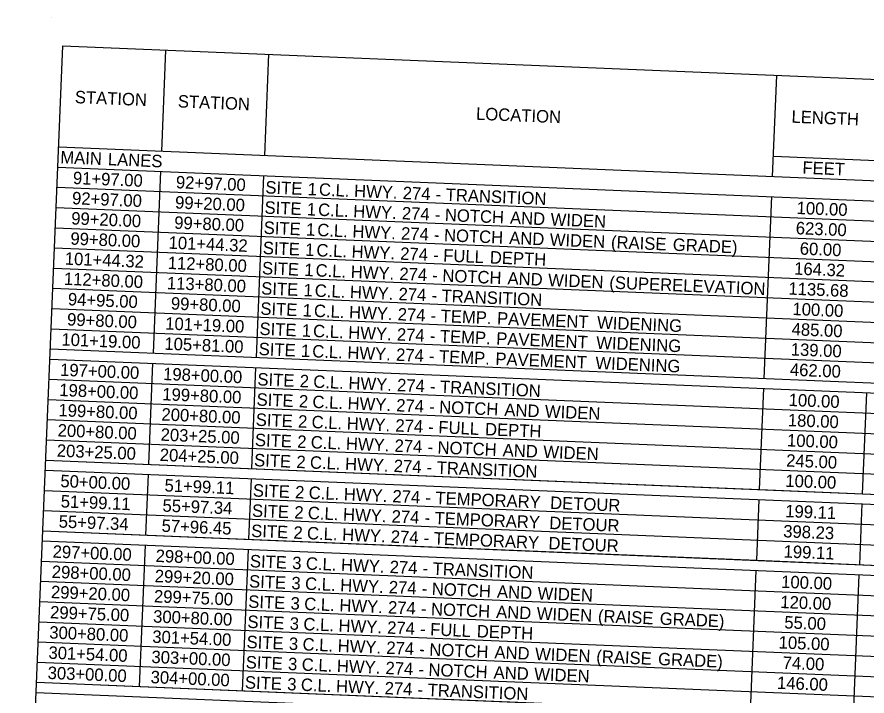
# Model space of a CAD drawing. Extents: x 1164179 to 1171425, y 1655958 to 1657208.
# Drawn here: x 1168004.2 to 1168414.3, y 1656519.5 to 1656846.8 of the extents above; entities that cross this region are included whole.
import ezdxf

# ---------------------------------------------------------------- set-up
doc = ezdxf.new("R2010")
doc.units = 0
doc.layers.add('Default', color=7, linetype='Continuous')

msp = doc.modelspace()

# ---------------------------------------------------------------- linework, layer by layer
at = {"layer": 'Default'}
for p, q in [((1168021.09, 1656846.81), (1168021.09, 1656846.81)), ((1168004.21, 1656297.14), (1168026.37, 1656832.93)), ((1168004.21, 1656297.14), (1168026.37, 1656832.93)), ((1168026.37, 1656832.93), (1169513.44, 1656771.41)), ((1168074.04, 1656782.16), (1168076.06, 1656830.87)), ((1168123.72, 1656780.11), (1168125.74, 1656828.82)), ((1168368.73, 1656769.97), (1168370.74, 1656818.68)), ((1168024.36, 1656784.22), (1169511.42, 1656722.7)), ((1168369.13, 1656779.72), (1168418.81, 1656777.66)), ((1168023.96, 1656774.48), (1169511.02, 1656712.96)), ((1168070.01, 1656684.75), (1168073.64, 1656772.42)), ((1168070.01, 1656684.75), (1168073.64, 1656772.42)), ((1168119.69, 1656682.69), (1168123.32, 1656770.37)), ((1168119.69, 1656682.69), (1168123.32, 1656770.37)), ((1168023.55, 1656764.74), (1169510.62, 1656703.22)), ((1168364.7, 1656672.56), (1168368.32, 1656760.23)), ((1168364.7, 1656672.56), (1168368.32, 1656760.23)), ((1168023.15, 1656754.99), (1169510.22, 1656693.48)), ((1168022.75, 1656745.25), (1169509.81, 1656683.74)), ((1168022.34, 1656735.51), (1169509.41, 1656673.99)), ((1168021.94, 1656725.77), (1169509.01, 1656664.25)), ((1168021.54, 1656716.03), (1169508.6, 1656654.51)), ((1168021.13, 1656706.29), (1169508.2, 1656644.77)), ((1168020.73, 1656696.54), (1169507.8, 1656635.03)), ((1168020.33, 1656686.8), (1169507.39, 1656625.29)), ((1168020.33, 1656686.8), (1169507.39, 1656625.29)), ((1168020.13, 1656681.93), (1169507.19, 1656620.41)), ((1168067.8, 1656631.17), (1168069.81, 1656679.88)), ((1168067.8, 1656631.17), (1168069.81, 1656679.88)), ((1168117.48, 1656629.11), (1168119.49, 1656677.82)), ((1168117.48, 1656629.11), (1168119.49, 1656677.82)), ((1168019.72, 1656672.19), (1169506.79, 1656610.67)), ((1168362.48, 1656618.98), (1168364.5, 1656667.69)), ((1168362.48, 1656618.98), (1168364.5, 1656667.69)), ((1168412.16, 1656616.92), (1168414.18, 1656665.63)), ((1168412.16, 1656616.92), (1168414.18, 1656665.63)), ((1168019.32, 1656662.45), (1169506.39, 1656600.93)), ((1168018.92, 1656652.71), (1169505.98, 1656591.19)), ((1168018.52, 1656642.97), (1169505.58, 1656581.45)), ((1168018.11, 1656633.22), (1168362.48, 1656618.98)), ((1168018.11, 1656633.22), (1169505.18, 1656571.71)), ((1168017.91, 1656628.35), (1169504.98, 1656566.84)), ((1168066.38, 1656597.07), (1168067.59, 1656626.3)), ((1168066.38, 1656597.07), (1168067.59, 1656626.3)), ((1168116.07, 1656595.02), (1168117.28, 1656624.24)), ((1168116.07, 1656595.02), (1168117.28, 1656624.24)), ((1168017.51, 1656618.61), (1169504.57, 1656557.09)), ((1168362.48, 1656618.98), (1169505.18, 1656571.71)), ((1168361.07, 1656584.88), (1168362.28, 1656614.11)), ((1168361.07, 1656584.88), (1168362.28, 1656614.11)), ((1168410.75, 1656582.83), (1168411.96, 1656612.05)), ((1168410.75, 1656582.83), (1168411.96, 1656612.05)), ((1168017.11, 1656608.87), (1169504.17, 1656547.35)), ((1168016.7, 1656599.13), (1168361.07, 1656584.88)), ((1168016.7, 1656599.13), (1169503.77, 1656537.61)), ((1168016.5, 1656594.26), (1169503.57, 1656532.74)), ((1168063.36, 1656524.01), (1168066.18, 1656592.2)), ((1168063.36, 1656524.01), (1168066.18, 1656592.2)), ((1168113.04, 1656521.95), (1168115.87, 1656590.15)), ((1168113.04, 1656521.95), (1168115.87, 1656590.15)), ((1168016.1, 1656584.52), (1169503.16, 1656523)), ((1168361.07, 1656584.88), (1169503.77, 1656537.61)), ((1168358.05, 1656511.82), (1168360.87, 1656580.01)), ((1168358.05, 1656511.82), (1168360.87, 1656580.01)), ((1168015.69, 1656574.77), (1169502.76, 1656513.26)), ((1168407.73, 1656509.76), (1168410.55, 1656577.96)), ((1168407.73, 1656509.76), (1168410.55, 1656577.96)), ((1168015.29, 1656565.03), (1169502.36, 1656503.51)), ((1168014.89, 1656555.29), (1169501.95, 1656493.77)), ((1168014.49, 1656545.55), (1169501.55, 1656484.03)), ((1168014.08, 1656535.81), (1169501.15, 1656474.29)), ((1168013.68, 1656526.07), (1168358.05, 1656511.82)), ((1168013.68, 1656526.07), (1169500.75, 1656464.55)), ((1168013.48, 1656521.19), (1169500.54, 1656459.68))]:
    msp.add_line(p, q, dxfattribs=at)

# ---------------------------------------------------------------- texts
for s, p in [('STATION', (1168032.04, 1656805.29)), ('STATION', (1168081.72, 1656803.24)), ('LOCATION', (1168225.57, 1656797.29)), ('LENGTH', (1168377.76, 1656795.87)), ('MAIN', (1168025.01, 1656776.31)), (' LANES', (1168045.74, 1656775.45)), ('FEET', (1168383.03, 1656771.26)), ('91+97.00', (1168031.1, 1656766.3)), ('92+97.00', (1168080.78, 1656764.25)), ('SITE', (1168123.94, 1656761.78)), (' 1', (1168142.11, 1656761.03)), (' C.L.', (1168147.56, 1656760.81)), (' HWY.', (1168164.51, 1656760.11)), (' 274', (1168187.97, 1656759.14)), (' TRANSITION', (1168208.71, 1656758.28)), ('92+97.00', (1168030.69, 1656756.56)), ('99+20.00', (1168080.38, 1656754.5)), (' -', (1168203.86, 1656758.48)), ('SITE', (1168123.54, 1656752.04)), (' 1', (1168141.71, 1656751.29)), (' C.L.', (1168147.15, 1656751.07)), (' HWY.', (1168164.1, 1656750.36)), (' 274', (1168187.57, 1656749.39)), ('100.00', (1168380.24, 1656751.86)), ('99+20.00', (1168030.29, 1656746.82)), ('99+80.00', (1168079.97, 1656744.76)), (' -', (1168203.46, 1656748.74)), (' NOTCH', (1168208.31, 1656748.54)), (' AND', (1168239.74, 1656747.24)), (' WIDEN', (1168259.31, 1656746.43)), ('SITE', (1168123.14, 1656742.3)), (' 1', (1168141.31, 1656741.55)), (' C.L.', (1168146.75, 1656741.32)), ('623.00', (1168379.83, 1656742.12)), ('99+80.00', (1168029.89, 1656737.08)), (' HWY.', (1168163.7, 1656740.62)), (' 274', (1168187.16, 1656739.65)), (' NOTCH', (1168207.9, 1656738.79)), (' AND', (1168239.34, 1656737.49)), (' WIDEN', (1168258.9, 1656736.68)), ('101+44.32', (1168077.26, 1656735.12)), ('SITE', (1168122.73, 1656732.56)), (' -', (1168203.05, 1656738.99)), (' (RAISE', (1168288.46, 1656735.46)), (' GRADE)', (1168318.27, 1656734.23)), (' 1', (1168140.9, 1656731.81)), (' C.L.', (1168146.35, 1656731.58)), (' HWY.', (1168163.3, 1656730.88)), (' 274', (1168186.76, 1656729.91)), (' FULL', (1168207.5, 1656729.05)), ('60.00', (1168381.76, 1656732.28)), ('101+44.32', (1168027.18, 1656727.43)), ('112+80.00', (1168076.84, 1656725.37)), (' -', (1168202.65, 1656729.25)), (' DEPTH', (1168230.01, 1656728.12)), ('SITE', (1168122.33, 1656722.82)), (' 1', (1168140.5, 1656722.07)), (' C.L.', (1168145.94, 1656721.84)), (' HWY.', (1168162.9, 1656721.14)), (' 274', (1168186.36, 1656720.17)), ('164.32', (1168379.05, 1656722.63)), ('112+80.00', (1168026.75, 1656717.69)), (' -', (1168202.25, 1656719.51)), (' NOTCH', (1168207.1, 1656719.31)), (' AND', (1168238.53, 1656718.01)), (' WIDEN', (1168258.1, 1656717.2)), (' (SUPERELEVATION', (1168287.65, 1656715.98)), ('113+80.00', (1168076.44, 1656715.63)), ('SITE', (1168121.93, 1656713.08)), (' 1', (1168140.1, 1656712.32)), (' C.L.', (1168145.54, 1656712.1)), ('1135.68', (1168376.28, 1656712.99)), ('94+95.00', (1168028.68, 1656707.85)), (' HWY.', (1168162.49, 1656711.4)), (' 274', (1168185.96, 1656710.43)), (' TRANSITION', (1168206.7, 1656709.57)), ('99+80.00', (1168078.36, 1656705.8)), (' -', (1168201.84, 1656709.77)), ('SITE', (1168121.52, 1656703.33)), (' 1', (1168139.7, 1656702.58)), (' C.L.', (1168145.14, 1656702.36)), (' HWY.', (1168162.09, 1656701.66)), (' 274', (1168185.55, 1656700.69)), (' TEMP.', (1168206.29, 1656699.83)), ('100.00', (1168378.22, 1656703.15)), ('99+80.00', (1168028.28, 1656698.11)), ('101+19.00', (1168075.63, 1656696.15)), (' -', (1168201.44, 1656700.03)), (' PAVEMENT', (1168233.48, 1656698.7)), (' WIDENING', (1168281.73, 1656696.71)), ('SITE', (1168121.12, 1656693.59)), (' 1', (1168139.29, 1656692.84)), (' C.L.', (1168144.73, 1656692.62)), (' HWY.', (1168161.69, 1656691.91)), ('485.00', (1168377.82, 1656693.41)), ('101+19.00', (1168025.55, 1656688.46)), (' 274', (1168185.15, 1656690.94)), (' TEMP.', (1168205.89, 1656690.09)), (' PAVEMENT', (1168233.08, 1656688.96)), ('105+81.00', (1168075.23, 1656686.41)), ('SITE', (1168120.72, 1656683.85)), (' -', (1168201.04, 1656690.29)), (' WIDENING', (1168281.32, 1656686.97)), ('139.00', (1168377.42, 1656683.67)), (' 1', (1168138.89, 1656683.1)), (' C.L.', (1168144.33, 1656682.87)), (' HWY.', (1168161.28, 1656682.17)), (' 274', (1168184.75, 1656681.2)), (' TEMP.', (1168205.49, 1656680.34)), (' PAVEMENT', (1168232.68, 1656679.22)), (' -', (1168200.63, 1656680.54)), (' WIDENING', (1168280.92, 1656677.22)), ('197+00.00', (1168024.94, 1656673.85)), ('198+00.00', (1168074.62, 1656671.8)), ('462.00', (1168377.01, 1656673.92)), ('SITE', (1168120.11, 1656669.24)), (' 2', (1168138.29, 1656668.49)), (' C.L.', (1168144.82, 1656668.22)), (' HWY.', (1168161.78, 1656667.51)), ('198+00.00', (1168024.54, 1656664.11)), (' 274', (1168185.24, 1656666.54)), (' TRANSITION', (1168205.98, 1656665.69)), ('199+80.00', (1168074.22, 1656662.05)), ('SITE', (1168119.71, 1656659.5)), (' 2', (1168137.88, 1656658.74)), (' -', (1168201.13, 1656665.89)), ('100.00', (1168376.41, 1656659.31)), (' C.L.', (1168144.42, 1656658.47)), (' HWY.', (1168161.37, 1656657.77)), (' 274', (1168184.84, 1656656.8)), (' NOTCH', (1168205.58, 1656655.94)), ('199+80.00', (1168024.13, 1656654.37)), ('200+80.00', (1168073.82, 1656652.31)), (' -', (1168200.72, 1656656.15)), (' AND', (1168237.01, 1656654.64)), (' WIDEN', (1168256.57, 1656653.83)), ('SITE', (1168119.31, 1656649.75)), (' 2', (1168137.48, 1656649)), (' C.L.', (1168144.02, 1656648.73)), (' HWY.', (1168160.97, 1656648.03)), (' 274', (1168184.43, 1656647.06)), ('180.00', (1168376.01, 1656649.57)), ('200+80.00', (1168023.73, 1656644.63)), ('203+25.00', (1168073.41, 1656642.57)), (' -', (1168200.32, 1656646.4)), (' FULL', (1168205.17, 1656646.2)), (' DEPTH', (1168227.68, 1656645.27)), ('SITE', (1168118.9, 1656640.01)), (' 2', (1168137.08, 1656639.26)), (' C.L.', (1168143.61, 1656638.99)), (' HWY.', (1168160.57, 1656638.29)), ('100.00', (1168375.6, 1656639.83)), ('203+25.00', (1168023.33, 1656634.88)), (' 274', (1168184.03, 1656637.32)), (' NOTCH', (1168204.77, 1656636.46)), (' AND', (1168236.2, 1656635.16)), (' WIDEN', (1168255.77, 1656634.35)), ('204+25.00', (1168073.01, 1656632.83)), ('SITE', (1168118.5, 1656630.27)), (' -', (1168199.92, 1656636.66)), ('245.00', (1168375.2, 1656630.09)), (' 2', (1168136.67, 1656629.52)), (' C.L.', (1168143.21, 1656629.25)), (' HWY.', (1168160.16, 1656628.55)), (' 274', (1168183.63, 1656627.58)), (' TRANSITION', (1168204.37, 1656626.72)), (' -', (1168199.51, 1656626.92)), ('50+00.00', (1168025.05, 1656620.18)), ('51+99.11', (1168075.3, 1656618.1)), ('100.00', (1168374.8, 1656620.34)), ('SITE', (1168117.9, 1656615.66)), (' 2', (1168136.07, 1656614.91)), (' C.L.', (1168142.61, 1656614.64)), (' HWY.', (1168159.56, 1656613.94)), ('51+99.11', (1168025.22, 1656610.41)), (' 274', (1168183.02, 1656612.96)), (' TEMPORARY', (1168203.76, 1656612.11)), (' DETOUR', (1168259.09, 1656609.82)), ('55+97.34', (1168074.33, 1656608.38)), ('SITE', (1168117.49, 1656605.92)), (' -', (1168198.91, 1656612.31)), ('199.11', (1168374.76, 1656605.71)), (' 2', (1168135.67, 1656605.17)), (' C.L.', (1168142.2, 1656604.9)), (' HWY.', (1168159.16, 1656604.19)), (' 274', (1168182.62, 1656603.22)), (' TEMPORARY', (1168203.36, 1656602.37)), ('55+97.34', (1168024.25, 1656600.69)), ('57+96.45', (1168073.89, 1656598.64)), (' -', (1168198.51, 1656602.57)), (' DETOUR', (1168258.68, 1656600.08)), ('SITE', (1168117.09, 1656596.18)), (' 2', (1168135.26, 1656595.42)), (' C.L.', (1168141.8, 1656595.15)), (' HWY.', (1168158.75, 1656594.45)), (' 274', (1168182.22, 1656593.48)), ('398.23', (1168373.78, 1656595.99)), (' -', (1168198.1, 1656592.82)), (' TEMPORARY', (1168202.96, 1656592.62)), (' DETOUR', (1168258.28, 1656590.33)), ('297+00.00', (1168021.31, 1656586.18)), ('199.11', (1168373.96, 1656586.23)), ('298+00.00', (1168071, 1656584.12)), ('SITE', (1168116.49, 1656581.56)), (' 3', (1168134.66, 1656580.81)), (' C.L.', (1168141.26, 1656580.54)), (' HWY.', (1168158.21, 1656579.84)), (' 274', (1168181.68, 1656578.87)), (' TRANSITION', (1168202.42, 1656578.01)), ('298+00.00', (1168020.91, 1656576.43)), ('299+20.00', (1168070.59, 1656574.38)), (' -', (1168197.56, 1656578.21)), ('SITE', (1168116.08, 1656571.82)), (' 3', (1168134.26, 1656571.07)), (' C.L.', (1168140.86, 1656570.8)), (' HWY.', (1168157.81, 1656570.1)), (' 274', (1168181.27, 1656569.12)), ('100.00', (1168372.78, 1656571.64)), ('299+20.00', (1168020.51, 1656566.69)), ('299+75.00', (1168070.19, 1656564.64)), (' -', (1168197.16, 1656568.47)), (' NOTCH', (1168202.01, 1656568.27)), (' AND', (1168233.44, 1656566.97)), (' WIDEN', (1168253.01, 1656566.16)), ('SITE', (1168115.68, 1656562.08)), (' 3', (1168133.85, 1656561.33)), (' C.L.', (1168140.45, 1656561.06)), (' HWY.', (1168157.41, 1656560.35)), ('120.00', (1168372.38, 1656561.89)), ('299+75.00', (1168020.1, 1656556.95)), (' 274', (1168180.87, 1656559.38)), (' NOTCH', (1168201.61, 1656558.53)), (' AND', (1168233.04, 1656557.22)), (' WIDEN', (1168252.61, 1656556.42)), ('300+80.00', (1168069.79, 1656554.9)), ('SITE', (1168115.28, 1656552.34)), (' -', (1168196.76, 1656558.73)), (' (RAISE', (1168282.17, 1656555.19)), (' GRADE)', (1168311.97, 1656553.96)), ('55.00', (1168374.3, 1656552.06)), (' 3', (1168133.45, 1656551.59)), (' C.L.', (1168140.05, 1656551.31)), (' HWY.', (1168157, 1656550.61)), (' 274', (1168180.47, 1656549.64)), (' FULL', (1168201.21, 1656548.78)), ('300+80.00', (1168019.7, 1656547.21)), ('301+54.00', (1168069.38, 1656545.15)), (' -', (1168196.35, 1656548.98)), (' DEPTH', (1168223.72, 1656547.85)), ('SITE', (1168114.87, 1656542.6)), (' 3', (1168133.05, 1656541.84)), (' C.L.', (1168139.65, 1656541.57)), (' HWY.', (1168156.6, 1656540.87)), (' 274', (1168180.06, 1656539.9)), ('105.00', (1168371.57, 1656542.41)), ('301+54.00', (1168019.3, 1656537.47)), (' -', (1168195.95, 1656539.24)), (' NOTCH', (1168200.8, 1656539.04)), (' AND', (1168232.24, 1656537.74)), (' WIDEN', (1168251.8, 1656536.93)), (' (RAISE', (1168281.36, 1656535.71)), ('303+00.00', (1168068.98, 1656535.41)), ('SITE', (1168114.47, 1656532.85)), (' 3', (1168132.64, 1656532.1)), (' C.L.', (1168139.25, 1656531.83)), (' GRADE)', (1168311.17, 1656534.48)), ('74.00', (1168373.5, 1656532.57)), ('303+00.00', (1168018.9, 1656527.73)), (' HWY.', (1168156.2, 1656531.13)), (' 274', (1168179.66, 1656530.16)), (' NOTCH', (1168200.4, 1656529.3)), (' AND', (1168231.83, 1656528)), ('304+00.00', (1168068.58, 1656525.67)), (' -', (1168195.55, 1656529.5)), (' WIDEN', (1168251.4, 1656527.19)), ('SITE', (1168114.07, 1656523.11)), (' 3', (1168132.24, 1656522.36)), (' C.L.', (1168138.84, 1656522.09)), (' HWY.', (1168155.79, 1656521.39)), (' 274', (1168179.26, 1656520.42)), (' TRANSITION', (1168200, 1656519.56)), ('146.00', (1168370.77, 1656522.93)), (' -', (1168195.15, 1656519.76))]:
    msp.add_text(s, height=6, rotation=357.6311, dxfattribs=at).set_placement(p)

doc.saveas('drawing.dxf')
